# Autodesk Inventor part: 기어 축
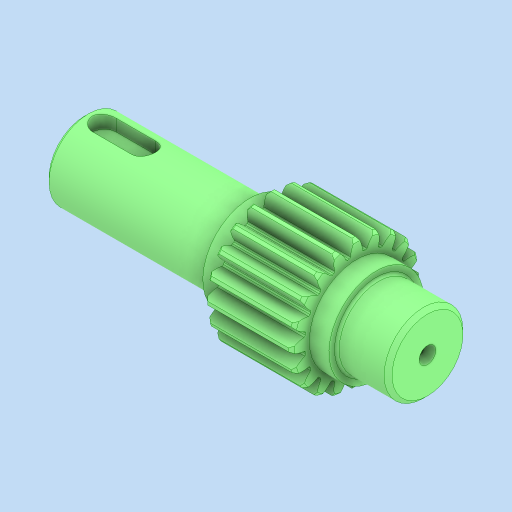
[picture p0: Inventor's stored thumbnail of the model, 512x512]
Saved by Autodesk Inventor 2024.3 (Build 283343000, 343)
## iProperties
Created: 2025-11
Part Number: 기어 축
Material: 강철, 합금
Document SubType Name: Modeling
Designer: PC2-02
Density: 7.73 g/cm^3
Appearance: 기본값
Author: jhkim
Sending System: Autodesk Inventor 2026
Preprocessor: ST-DEVELOPER v20.1
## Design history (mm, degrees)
node "기어 축1"
node "솔리드2"
node "솔리드1"
